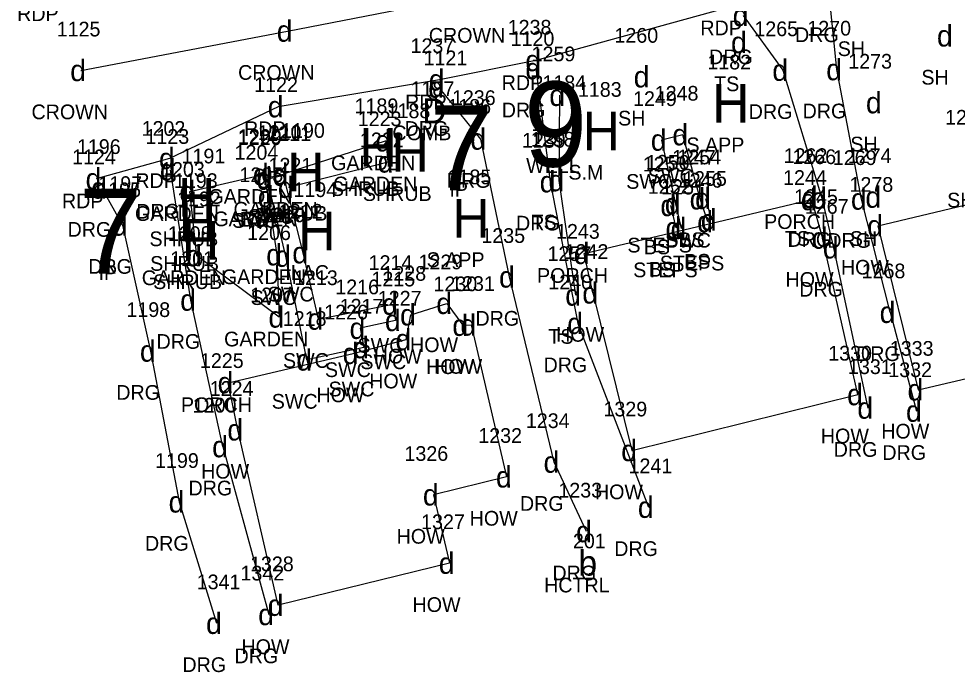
# Model space of a CAD drawing. Extents: x 461160 to 461373, y 202903 to 203086.
# Drawn here: x 461208.35 to 461256.86, y 202903.01 to 202936.79 of the extents above; entities that cross this region are included whole.
import ezdxf

# ---------------------------------------------------------------- set-up
doc = ezdxf.new("R2010")
doc.units = 0
for name, color, linetype in [('Level 1', 7, 'Continuous'), ('Level 11', 7, 'Continuous'), ('Level 12', 7, 'Continuous'), ('Level 13', 7, 'Continuous'), ('Level 14', 7, 'Continuous'), ('Level 15', 7, 'Continuous'), ('Level 18', 7, 'Continuous'), ('Level 46', 7, 'Continuous'), ('Level 47', 7, 'Continuous'), ('Level 48', 7, 'Continuous'), ('Level 49', 7, 'Continuous')]:
    doc.layers.add(name, color=color, linetype=linetype)

msp = doc.modelspace()

# ---------------------------------------------------------------- linework, layer by layer
at = {"layer": 'Level 11'}
for points in [[(461270.507, 202944.203), (461260.148, 202941.513), (461250.261, 202938.68), (461245.353, 202937.463), (461235.083, 202934.632), (461230.09, 202933.632), (461221.765, 202932.249), (461216.144, 202929.568), (461212.35, 202928.516)], [(461253.4, 202921.618), (461251.915, 202927.474), (461250.638, 202934.166), (461250.245, 202938.109)], [(461245.801, 202936.964), (461247.852, 202934.135), (461249.857, 202927.523), (461250.466, 202924.952)], [(461235.085, 202934.216), (461235.825, 202928.369), (461237.247, 202921.042), (461240.901, 202911.54)], [(461237.704, 202910.282), (461236.025, 202913.875), (461233.725, 202923.447), (461232.242, 202930.576), (461230.062, 202933.261)], [(461218.893, 202914.673), (461217.241, 202922.251), (461216.191, 202928.983)], [(461212.641, 202928.045), (461213.71, 202926.132), (461215.16, 202919.616), (461216.643, 202911.815)], [(461250.466, 202924.952), (461252.246, 202916.667)], [(461253.4, 202921.618), (461254.761, 202916.508)], [(461218.893, 202914.673), (461221.272, 202905.995)], [(461216.643, 202911.815), (461218.578, 202905.541)]]:
    msp.add_lwpolyline(points, dxfattribs=at)
at = {"layer": 'Level 12'}
for points in [[(461243.966, 202926.303), (461243.576, 202927.486), (461242.685, 202930.802), (461241.569, 202930.524), (461242.291, 202927.232), (461242.59, 202925.952)], [(461222.29, 202928.083), (461227.447, 202929.392), (461227.334, 202930.483), (461222.012, 202928.768)], [(461217.196, 202927.863), (461220.995, 202928.748), (461221.249, 202927.589), (461221.687, 202924.595), (461221.803, 202921.376), (461217.548, 202924.545), (461217.196, 202927.863)], [(461222.018, 202928.717), (461223.038, 202924.699), (461223.824, 202921.267), (461227.678, 202922.047), (461227.825, 202921.199), (461225.995, 202920.791), (461226.181, 202919.794), (461223.243, 202919.156), (461222.151, 202924.518), (461221.194, 202928.506), (461222.018, 202928.717)]]:
    msp.add_lwpolyline(points, dxfattribs=at)
at = {"layer": 'Level 13'}
for points in [[(461252.754, 202926.088), (461259.473, 202927.696), (461266.663, 202929.394), (461267.163, 202927.056)], [(461238.03, 202922.62), (461237.583, 202924.663), (461249.321, 202927.447), (461249.891, 202925.457)], [(461252.754, 202926.088), (461254.839, 202917.613), (461261.308, 202919.121), (461261.843, 202917.458), (461269.045, 202919.243), (461267.163, 202927.056)], [(461238.03, 202922.62), (461240.038, 202914.476), (461251.718, 202917.364), (461249.891, 202925.457)], [(461219.68, 202915.54), (461219.176, 202917.98), (461225.641, 202919.49), (461228.37, 202920.206), (461228.608, 202921.49), (461230.48, 202922.081), (461231.311, 202920.948), (461231.728, 202920.965), (461233.565, 202913.109)], [(461233.565, 202913.109), (461229.787, 202912.178), (461230.609, 202908.647), (461221.764, 202906.472), (461219.68, 202915.54)]]:
    msp.add_lwpolyline(points, dxfattribs=at)
at = {"layer": 'Level 48'}
for points in [[(461211.555, 202934.121), (461222.234, 202936.16), (461232.093, 202938.078), (461241.693, 202939.978), (461251.734, 202942.643), (461261.209, 202945.054), (461270.211, 202947.385), (461280.824, 202950.466), (461289.045, 202954.252), (461296.764, 202959.518)], [(461237.145, 202922.513), (461236.279, 202928.426), (461236.324, 202932.837)], [(461237.145, 202922.513), (461236.279, 202928.426), (461236.324, 202932.837)], [(461221.173, 202928.567), (461222.012, 202928.768)], [(461221.173, 202928.567), (461222.012, 202928.768)], [(461243.856, 202927.51), (461244.153, 202926.396)], [(461243.856, 202927.51), (461244.153, 202926.396)], [(461242.328, 202925.985), (461242.063, 202927.14)], [(461242.328, 202925.985), (461242.063, 202927.14)]]:
    msp.add_lwpolyline(points, dxfattribs=at)

# ---------------------------------------------------------------- texts
at = {"layer": 'Level 1'}
msp.add_text('b', height=1.3, dxfattribs=at).set_placement((461237.28, 202908.007))
at = {"layer": 'Level 14'}
for p in [(461244.19, 202931.416), (461237.499, 202930), (461225.958, 202929.154), (461227.611, 202928.896), (461222.22, 202927.879), (461216.58, 202926.558), (461216.617, 202925.284), (461230.76, 202925.479), (461222.794, 202924.817), (461216.773, 202924.341)]:
    msp.add_text('H', height=2, dxfattribs=at).set_placement(p)
at = {"layer": 'Level 15'}
for s, height, p in [('9', 4.4, (461234.462, 202929.148)), ('D', 1.3, (461229.2, 202931.386))]:
    msp.add_text(s, height=height, dxfattribs=at).set_placement(p)
at = {"layer": 'Level 18'}
for p in [(461229.588, 202927.921), (461211.451, 202923.611)]:
    msp.add_text('7', height=4.4, dxfattribs=at).set_placement(p)
at = {"layer": 'Level 46'}
for s, p in [(' RDP  ', (461207.983, 202936.672)), (' RDP  ', (461243.301, 202935.943)), (' CROWN  ', (461229.263, 202935.558)), (' DRG  ', (461248.193, 202935.589)), (' SH  ', (461250.403, 202934.867)), (' DRG  ', (461243.749, 202934.444)), (' CROWN  ', (461219.404, 202933.64)), (' SH  ', (461254.727, 202933.391)), (' RDP  ', (461233.031, 202933.112)), (' TS  ', (461244.014, 202933.051)), (' RDP  ', (461228.038, 202932.112)), (' CROWN  ', (461208.725, 202931.601)), (' DRG  ', (461233.033, 202931.696)), (' DRG  ', (461245.8, 202931.615)), (' DRG  ', (461248.586, 202931.646)), (' SH  ', (461239.049, 202931.276)), (' RDP  ', (461219.713, 202930.729)), (' COMB  ', (461227.379, 202930.516)), (' DRG  ', (461228.01, 202930.741)), (' TS  ', (461234.622, 202930.317)), (' S.APP  ', (461242.581, 202929.896)), (' SH  ', (461251.055, 202929.937)), (' GARDEN  ', (461224.211, 202928.963)), (' WELL  ', (461234.296, 202928.828)), (' S.M  ', (461236.48, 202928.48)), (' RDP  ', (461214.092, 202928.048)), (' DRG  ', (461230.19, 202928.056)), (' SWC  ', (461239.469, 202928.004)), (' SWC  ', (461240.585, 202928.282)), (' SHRUB  ', (461224.2, 202927.634)), (' GARDEN  ', (461224.324, 202927.872)), (' IP  ', (461230.328, 202927.601)), (' RDP  ', (461210.298, 202926.996)), (' GARDEN  ', (461217.872, 202927.228)), (' SHRUB  ', (461225.853, 202927.376)), (' SH  ', (461256.06, 202927.04)), (' GARDEN  ', (461219.167, 202926.563)), (' GARDEN  ', (461214.073, 202926.343)), (' DRG  ', (461214.139, 202926.463)), (' GARDEN  ', (461218.126, 202926.069)), (' BS  ', (461219.483, 202926.047)), (' SWC  ', (461219.918, 202926.197)), (' BS  ', (461220.322, 202926.248)), (' SHRUB  ', (461220.462, 202926.359)), (' DRG  ', (461210.589, 202925.525)), (' SWC  ', (461219.094, 202925.986)), (' DRG  ', (461233.773, 202925.849)), (' TS  ', (461234.577, 202925.906)), (' PORCH  ', (461246.596, 202925.927)), (' SHRUB  ', (461214.822, 202925.038)), (' TS  ', (461247.667, 202925.057)), (' SH  ', (461251.026, 202925.053)), (' STEPS  ', (461239.53, 202924.712)), (' BS  ', (461240.373, 202924.62)), (' SWC  ', (461241.476, 202924.966)), (' BS  ', (461242.166, 202924.99)), (' DRG  ', (461247.805, 202925.003)), (' DRG  ', (461249.863, 202924.954)), (' DRG  ', (461211.658, 202923.612)), (' SHRUB  ', (461214.859, 202923.764)), (' S.APP  ', (461229.151, 202923.959)), (' STEPS  ', (461241.205, 202923.783)), (' BS  ', (461242.463, 202923.876)), (' IP  ', (461212.191, 202923.291)), (' LILAC  ', (461221.281, 202923.297)), (' PORCH  ', (461234.858, 202923.143)), (' STEPS  ', (461239.829, 202923.432)), (' BS  ', (461240.638, 202923.465)), (' HOW  ', (461250.567, 202923.568)), (' GARDEN  ', (461214.425, 202923.025)), (' SHRUB  ', (461215.015, 202922.821)), (' GARDEN  ', (461218.564, 202923.075)), (' HOW  ', (461247.704, 202922.937)), (' SWC  ', (461220.938, 202922.179)), (' DRG  ', (461248.414, 202922.432)), (' SWC  ', (461220.051, 202921.998)), (' DRG  ', (461231.673, 202920.927)), (' DRG  ', (461215.189, 202919.731)), (' GARDEN  ', (461218.68, 202919.856)), (' TS  ', (461235.443, 202919.993)), (' HOW  ', (461235.843, 202920.1)), (' SWC  ', (461225.578, 202919.527)), (' HOW  ', (461228.293, 202919.561)), (' SWC  ', (461221.724, 202918.747)), (' HOW  ', (461226.421, 202918.97)), (' DRG  ', (461251.348, 202919.098)), (' SWC  ', (461223.895, 202918.271)), (' SWC  ', (461225.725, 202918.679)), (' HOW  ', (461229.124, 202918.428)), (' HOW  ', (461229.541, 202918.445)), (' DRG  ', (461235.195, 202918.522)), (' SWC  ', (461224.081, 202917.274)), (' HOW  ', (461226.183, 202917.686)), (' DRG  ', (461213.108, 202917.096)), (' HOW  ', (461223.454, 202916.97)), (' PORCH  ', (461216.451, 202916.46)), (' SWC  ', (461221.143, 202916.636)), (' HOW  ', (461249.531, 202914.844)), (' HOW  ', (461252.652, 202915.093)), (' DRG  ', (461250.194, 202914.147)), (' DRG  ', (461252.709, 202913.988)), (' HOW  ', (461217.493, 202913.02)), (' DRG  ', (461216.841, 202912.153)), (' HOW  ', (461237.851, 202911.956)), (' DRG  ', (461233.973, 202911.355)), (' HOW  ', (461231.378, 202910.589)), (' HOW  ', (461227.6, 202909.658)), (' DRG  ', (461214.591, 202909.295)), (' DRG  ', (461238.849, 202909.02)), (' DRG  ', (461235.652, 202907.762)), (' HCTRL  ', (461235.223, 202907.137)), (' HOW  ', (461228.422, 202906.127)), (' HOW  ', (461219.577, 202903.952)), (' DRG  ', (461219.22, 202903.475)), (' DRG  ', (461216.526, 202903.021))]:
    msp.add_text(s, height=0.76, dxfattribs=at).set_placement(p)
at = {"layer": 'Level 47'}
for p in [(461245.251, 202936.414), (461221.684, 202935.61), (461255.813, 202935.361), (461245.166, 202935.021), (461234.533, 202934.082), (461211.005, 202933.571), (461234.535, 202933.666), (461247.302, 202933.585), (461250.088, 202933.616), (461229.54, 202933.082), (461240.135, 202933.246), (461229.512, 202932.711), (461235.774, 202932.287), (461221.215, 202931.699), (461252.141, 202931.907), (461231.692, 202930.026), (461242.135, 202930.252), (461226.784, 202929.933), (461241.019, 202929.974), (461215.594, 202929.018), (461226.897, 202928.842), (461215.641, 202928.433), (461220.445, 202928.198), (461221.462, 202928.218), (461221.468, 202928.167), (461211.8, 202927.966), (461220.623, 202928.017), (461220.644, 202927.956), (461235.275, 202927.819), (461235.729, 202927.876), (461212.091, 202927.495), (461216.646, 202927.313), (461221.74, 202927.533), (461220.699, 202927.039), (461241.513, 202926.59), (461241.741, 202926.682), (461243.026, 202926.936), (461243.306, 202926.96), (461248.771, 202926.897), (461248.819, 202927.027), (461249.307, 202926.973), (461251.365, 202926.924), (461252.112, 202927.023), (461243.416, 202925.753), (461243.603, 202925.846), (461213.16, 202925.582), (461241.778, 202925.435), (461242.04, 202925.402), (461252.204, 202925.538), (461249.341, 202924.907), (461249.916, 202924.402), (461216.998, 202923.995), (461221.137, 202924.045), (461221.601, 202923.968), (461222.488, 202924.149), (461237.033, 202924.113), (461233.175, 202922.897), (461236.595, 202921.963), (461237.48, 202922.07), (461216.691, 202921.701), (461227.128, 202921.497), (461229.93, 202921.531), (461221.253, 202920.826), (461228.058, 202920.94), (461252.85, 202921.068), (461223.274, 202920.717), (461227.275, 202920.649), (461230.761, 202920.398), (461231.178, 202920.415), (461236.697, 202920.492), (461225.445, 202920.241), (461227.82, 202919.656), (461214.61, 202919.066), (461225.091, 202918.94), (461225.631, 202919.244), (461222.693, 202918.606), (461218.626, 202917.43), (461254.289, 202917.063), (461251.168, 202916.814), (461251.696, 202916.117), (461254.211, 202915.958), (461219.13, 202914.99), (461218.343, 202914.123), (461239.488, 202913.926), (461235.475, 202913.325), (461233.015, 202912.559), (461229.237, 202911.628), (461216.093, 202911.265), (461240.351, 202910.99), (461237.154, 202909.732), (461230.059, 202908.097), (461221.214, 202905.922), (461220.722, 202905.445), (461218.028, 202904.991)]:
    msp.add_text('d', height=1.1, dxfattribs=at).set_placement(p)
at = {"layer": 'Level 49'}
for s, p in [(' 1125 ', (461210.027, 202935.881)), (' 1238 ', (461233.341, 202935.976)), (' 1265 ', (461246.09, 202935.895)), (' 1270 ', (461248.831, 202935.926)), (' 1120 ', (461233.492, 202935.392)), (' 1260 ', (461238.86, 202935.556)), (' 1237 ', (461228.318, 202935.021)), (' 1121 ', (461228.992, 202934.392)), (' 1259 ', (461234.577, 202934.597)), (' 1182 ', (461243.662, 202934.176)), (' 1273 ', (461250.947, 202934.217)), (' 1122 ', (461220.237, 202933.009)), (' 1187 ', (461228.322, 202932.796)), (' 1184 ', (461235.134, 202933.108)), (' 1236 ', (461230.459, 202932.336)), (' 1183 ', (461236.971, 202932.76)), (' 1248 ', (461240.941, 202932.562)), (' 1189 ', (461225.427, 202931.914)), (' 1186 ', (461230.221, 202931.881)), (' 1249 ', (461239.822, 202932.284)), (' 1188 ', (461227.083, 202931.656)), (' 1223 ', (461225.59, 202931.243)), (' 1275 ', (461255.952, 202931.32)), (' 1202 ', (461214.417, 202930.743)), (' 1210 ', (461220.421, 202930.528)), (' 1211 ', (461220.92, 202930.477)), (' 1190 ', (461221.629, 202930.639)), (' 1123 ', (461214.616, 202930.328)), (' 1220 ', (461219.387, 202930.266)), (' 1209 ', (461219.396, 202930.327)), (' 1222 ', (461225.703, 202930.152)), (' 1239 ', (461234.078, 202930.129)), (' 1258 ', (461234.535, 202930.186)), (' 1196 ', (461211.074, 202929.805)), (' 1204 ', (461219.221, 202929.508)), (' 1124 ', (461210.822, 202929.276)), (' 1191 ', (461216.482, 202929.318)), (' 1250 ', (461240.484, 202928.992)), (' 1247 ', (461241.832, 202929.246)), (' 1254 ', (461242.112, 202929.27)), (' 1262 ', (461247.607, 202929.337)), (' 1266 ', (461248.056, 202929.283)), (' 1269 ', (461250.15, 202929.234)), (' 1274 ', (461250.918, 202929.333)), (' 1203 ', (461215.422, 202928.623)), (' 1221 ', (461220.977, 202928.843)), (' 1253 ', (461240.319, 202928.9)), (' 1193 ', (461216.089, 202928.044)), (' 1205 ', (461219.475, 202928.349)), (' 1185 ', (461230.232, 202928.239)), (' 1246 ', (461242.183, 202928.063)), (' 1255 ', (461242.409, 202928.156)), (' 1244 ', (461247.577, 202928.207)), (' 1195 ', (461212.123, 202927.571)), (' 1197 ', (461212.182, 202927.892)), (' 1194 ', (461222.266, 202927.577)), (' 1252 ', (461240.584, 202927.745)), (' 1251 ', (461241.277, 202927.712)), (' 1278 ', (461251.01, 202927.848)), (' 1192 ', (461216.245, 202927.101)), (' 1245 ', (461248.147, 202927.217)), (' 1267 ', (461248.704, 202926.712)), (' 1219 ', (461220.62, 202926.278)), (' 1212 ', (461221.51, 202926.459)), (' 1208 ', (461215.774, 202925.305)), (' 1206 ', (461219.874, 202925.355)), (' 1235 ', (461231.981, 202925.207)), (' 1243 ', (461235.839, 202925.423)), (' 1257 ', (461235.401, 202924.273)), (' 1242 ', (461236.286, 202924.38)), (' 1201 ', (461215.898, 202924.011)), (' 1214 ', (461226.15, 202923.807)), (' 1229 ', (461228.733, 202923.841)), (' 1228 ', (461226.864, 202923.25)), (' 1268 ', (461251.638, 202923.378)), (' 1213 ', (461222.296, 202923.027)), (' 1215 ', (461226.297, 202922.959)), (' 1230 ', (461229.504, 202922.708)), (' 1231 ', (461230.415, 202922.725)), (' 1240 ', (461235.44, 202922.802)), (' 1207 ', (461220.029, 202922.136)), (' 1216 ', (461224.428, 202922.551)), (' 1227 ', (461226.626, 202921.966)), (' 1198 ', (461213.632, 202921.376)), (' 1226 ', (461223.858, 202921.25)), (' 1217 ', (461224.653, 202921.554)), (' 1218 ', (461221.715, 202920.916)), (' 1333 ', (461253.095, 202919.373)), (' 1225 ', (461217.432, 202918.74)), (' 1330 ', (461249.911, 202919.124)), (' 1331 ', (461250.933, 202918.427)), (' 1332 ', (461253.017, 202918.268)), (' 1224 ', (461217.936, 202917.3)), (' 1200 ', (461217.056, 202916.433)), (' 1329 ', (461238.291, 202916.236)), (' 1234 ', (461234.281, 202915.635)), (' 1232 ', (461231.821, 202914.869)), (' 1326 ', (461228.004, 202913.938)), (' 1199 ', (461215.112, 202913.575)), (' 1241 ', (461239.588, 202913.3)), (' 1233 ', (461235.96, 202912.042)), (' 1327 ', (461228.865, 202910.407)), (' 201 ', (461236.713, 202909.417)), (' 1328 ', (461220.02, 202908.232)), (' 1342 ', (461219.528, 202907.755)), (' 1341 ', (461217.265, 202907.301))]:
    msp.add_text(s, height=0.76, dxfattribs=at).set_placement(p)

doc.saveas('drawing.dxf')
